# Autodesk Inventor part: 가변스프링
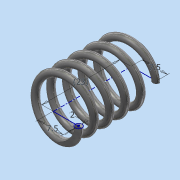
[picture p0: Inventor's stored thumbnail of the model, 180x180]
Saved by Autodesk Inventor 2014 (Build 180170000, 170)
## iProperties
Created: 2026-06
Part Number: 가변스프링
Material: 강철, 합금
Document SubType Name: Modeling
Designer: dg
Density: 7.85 g/cm^3
Appearance: 반연마
Mass: 5.70349 g
Surface Area: 14.7818 cm^2
Volume: 0.726559 cm^3
Author: dg
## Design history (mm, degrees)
sketch "스케치1"
  geometry: L1 (0, 0)-(0, 23); L2 (0, 0)-(7.5, 0); L3 (0, 23)-(7.5, 23); C1 r 1 at (7.5, 0)
  constraints: 6 end point, 1 centre point, 1 coincident, 1 parallel, 1 perpendicular, 1 vertical
  dimensions: "d3" = 23 distance of L1.start L1.end (derived); "d4" = 7.5 distance of L1.end L3.end; "d5" = 7.5 distance of L1.start L2.end; "d6" = 2 diameter of C1
feature "코일1" sketch "스케치1" pitch "d7" = 10; turns "d9" = 5; dims "d8" = 23 (= d3), "d10" = 0, angle "d11" = 90 deg, angle "d12" = 90 deg, "d13" = 0, "d14" = 0
node "작업 평면1"
feature "분할1"
feature "분할2"
node "솔리드1"
other parameters: "d15" = 0
